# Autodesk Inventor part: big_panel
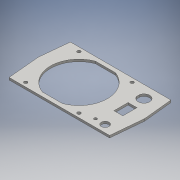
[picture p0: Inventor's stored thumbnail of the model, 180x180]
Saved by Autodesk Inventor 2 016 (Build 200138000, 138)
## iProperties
Created: 2016-12
Part Number: big_panel
Material: Типовые
Document SubType Name: Modeling
Designer: admin
Density: 1 g/cm^3
Appearance: По умолчанию
Author: admin
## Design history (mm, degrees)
sketch "Эскиз1"
  geometry: L1 (-68, -41.5)-(68, -41.5); L2 (68, 41.5)-(-68, 41.5); L3 (-68, 41.5)-(-72, 2); L4 (-72, 2)-(-68, -41.5); L5 (68, 41.5)-(72, 2); L6 (72, 2)-(68, -41.5); 2 further points
  constraints: 12 end point, 1 horizontal, 1 midpoint, 1 parallel, 1 vertical alignment
extrude "Выдавливание1" new body sketch "Эскиз1" distance "d20" = 3; taper "d21" = 0 deg
sketch "Эскиз2"
  geometry: L1 (-55, -40)-(25, -40); L2 (25, -40)-(25, 40); L3 (25, 40)-(-55, 40); L4 (-55, 40)-(-55, -40); L5 (-55, -40)-(25, 40); L6 (25, -40)-(-55, 40); L7 (-51, -36)-(21, 36); L8 (21, -36)-(-51, 36); L9 (-68, 41.5)-(-72, 2) reference; L10 (-72, 2)-(-72, 44.842); L11 (-28.647, 36)-(-1.353, 36); L12 (-1.353, 36)-(-28.647, 36); L13 (-28.647, -36)-(-1.353, -36); C1 r 2.25 at (-51, 36); C2 r 2.25 at (21, 36); C3 r 2.25 at (-51, -36); C4 r 2.25 at (21, -36); A1 r 38.5 centre (-15, 0) between (-28.647, 36) and (-28.647, -36); A2 r 38.5 centre (-15, 0) between (-1.353, -36) and (-1.353, 36); 2 further points
  constraints: 24 end point, 6 centre point, 5 coincident, 4 midpoint, 4 point on circle, 2 horizontal, 2 parallel, 1 perpendicular, 1 vertical
  dimensions: "d26" = 80 distance of L3.end L2.end; "d27" = 80 distance of L2.end L1.end; "d28" = 72 distance of L8.end L7.end; "d29" = 72 distance of L7.end L8.start; "d30" = 4.5 diameter of C1; "d31" = 4.5 diameter of C2; "d32" = 4.5 diameter of C3; "d33" = 4.5 diameter of C4; "d35" = 17 distance between parallel lines of L10 L4
extrude "Выдавливание2" cut sketch "Эскиз2" distance "d36" = 10; taper "d37" = 0 deg
sketch "Эскиз3"
  geometry: L1 (40.5, 27.142)-(40.5, 22.858); L2 (68, -41.5)-(72, 2) reference; L3 (41.95, -9.6)-(54.05, -9.6); L4 (54.05, -9.6)-(54.05, 9.6); L5 (54.05, 9.6)-(41.95, 9.6); L6 (41.95, 9.6)-(41.95, -9.6); L7 (41.95, -9.6)-(54.05, 9.6); L8 (54.05, -9.6)-(41.95, 9.6); L9 (-68, -41.5)-(68, -41.5) reference; L10 (72, 2)-(72, -56.036); L11 (-72, 2)-(-68, -41.5) reference; L12 (-72, 2)-(-72, -53.21); C1 r 5.25 at (52, -31.5); C2 r 2 at (39, -31.5); A1 r 7.8 centre (48, 25) between (40.5, 22.858) and (40.5, 27.142); 4 further points
  constraints: 18 end point, 4 midpoint, 3 centre point, 3 vertical, 2 parallel, 2 point on circle, 1 horizontal, 1 perpendicular
  dimensions: "d38" = 15.6 diameter of A1; "d40" = 7.5 distance from line of A1.centre L1; "d41" = 48 horizontal distance of point (0, 0) A1.centre; "d42" = 25 vertical distance of point (0, 0) A1.centre; "d43" = 12.1 distance of L5.end L4.end; "d44" = 19.2 distance of L4.end L3.end; "d45" = 10.5 diameter of C1; "d46" = 4 diameter of C2; "d47" = 13 distance of C2.centre C1.centre; "d48" = 10 distance from line of L9 C1.centre; "d49" = 20 distance from line of L10 C1.centre; "d50" = 48 distance of point (0, 0) point (48, 0); "d53" = 52 horizontal distance of point (0, 0) C1.centre (derived)
extrude "Выдавливание3" cut sketch "Эскиз3" distance "d51" = 10; taper "d52" = 0 deg
node "Твердое тело1"
other parameters: "d34" = 77
